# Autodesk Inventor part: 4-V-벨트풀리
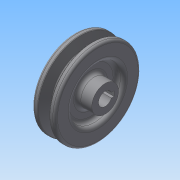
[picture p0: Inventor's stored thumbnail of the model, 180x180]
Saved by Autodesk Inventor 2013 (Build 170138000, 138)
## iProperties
Created: 2015-02
Part Number: 4-V-벨트풀리
Material: 일반
Document SubType Name: Modeling
Designer: Administrator
Density: 1 g/cm^3
Author: Administrator
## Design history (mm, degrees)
sketch "스케치1"
  geometry: L1 (0, 0)-(25, 0); L2 (0, 0)-(0, 11); L3 (0, 11)-(6, 11); L4 (6, 11)-(6, 21.5); L5 (6, 21.5)-(0, 21.5); L6 (0, 21.5)-(0, 35.2); L7 (0, 35.2)-(4.675, 35.2); L8 (4.675, 35.2)-(7.426, 26.2); L9 (7.426, 26.2)-(11.574, 26.2); L10 (11.574, 26.2)-(14.325, 35.2); L11 (14.325, 35.2)-(19, 35.2); L12 (25, 11)-(25, 0); L13 (19, 35.2)-(19, 21.5); L14 (19, 21.5)-(13, 21.5); L15 (13, 21.5)-(13, 11); L16 (13, 11)-(25, 11); 2 further points
  constraints: 32 end point, 8 parallel, 5 collinear, 4 perpendicular, 2 equal length, 2 point on line, 1 horizontal, 1 horizontal alignment
  dimensions: "d0" = 25 distance of L1.start L1.end; "d3" = 43 diameter of L5 L1; "d4" = 65 diameter of point (5.5, 32.5) L1; "d5" = 8 distance of point (13.5, 32.5) point (5.5, 32.5); "d6" = 34 deg angle of L10 L8; "d7" = 19 distance between parallel lines of L13 L6; "d8" = 6 distance between parallel lines of L6 L4; "d9" = 6 distance between parallel lines of L15 L13; "d10" = 2.7 distance from line of point (13.5, 32.5) L11; "d11" = 6.3 distance from line of L9 point (13.5, 32.5); "d12" = 22 diameter of L16 L1
revolve "회전1" sketch "스케치1" stored, may be unused: angle "d13" = 90 deg
sketch "스케치2"
  geometry: L1 (-2, 5.123)-(-2, 7.3); L2 (-2, 7.3)-(2, 7.3); L3 (2, 7.3)-(2, 5.123); C1 r 11 at (0, 0) reference; A1 r 5.5 centre (0, 0) between (-2, 5.123) and (2, 5.123)
  constraints: 6 end point, 2 parallel, 2 point on circle, 1 centre point, 1 coincident, 1 perpendicular, 1 vertical
  dimensions: "d14" = 12.8 dimension on A1 L2; "d16" = 11 diameter of A1; "d17" = 4 distance of L1.end L2.end
extrude "돌출1" cut sketch "스케치2" stored distance "d18" = 10; taper "d19" = 0 deg
fillet "모깎기1" dims "d20" = 3, "d21" = 2, "d22" = 1, "d23" = 0.5
node "솔리드1"
